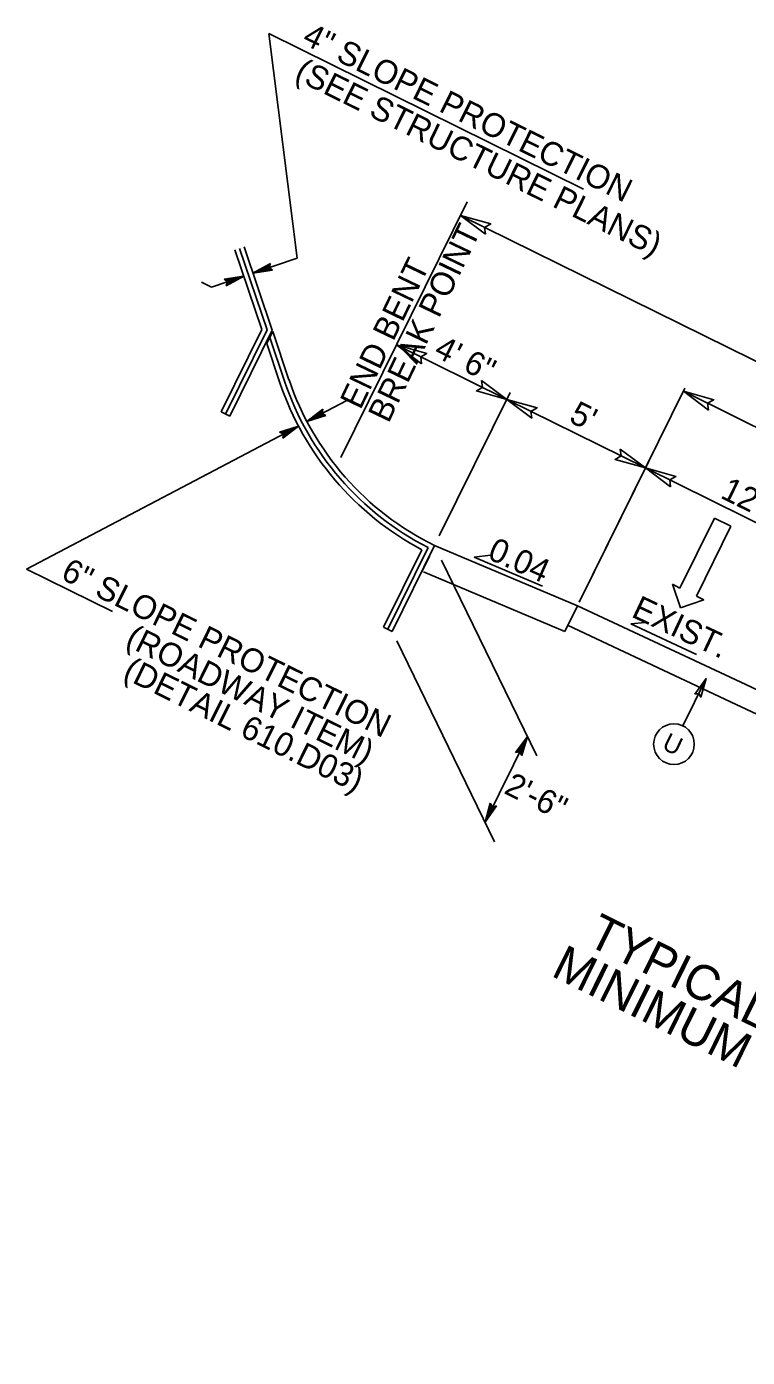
# Model space of a CAD drawing. Extents: x 1518247 to 1523638, y 635234 to 639927.
# Drawn here: x 1518247 to 1518587, y 636846 to 637473 of the extents above; entities that cross this region are included whole.
import ezdxf

# ---------------------------------------------------------------- set-up
doc = ezdxf.new("R2010")
doc.units = 0
for name, color, linetype in [('DTM TIN Hull White', 7, 'Continuous'), ('Prop Dimension', 7, 'Continuous'), ('Prop Dimension Text', 7, 'Continuous'), ('Prop Lane Arrow CELL', 7, 'Continuous'), ('Prop Shade Light', 7, 'Continuous'), ('Typical ID Circle CELL', 7, 'Continuous'), ('Typical Pavement Slope CELL', 7, 'Continuous'), ('Typical Pavement Slope Information CELL', 7, 'Continuous'), ('Typical Structure Recommendation Sheet 2 CELL', 7, 'Continuous'), ('Typical Text ID Circle CELL', 7, 'Continuous')]:
    doc.layers.add(name, color=color, linetype=linetype)

# ---------------------------------------------------------------- blocks, each defined once
blk = doc.blocks.new('TERMINATOR')
at = {"layer": 'Prop Shade Light'}
blk.add_lwpolyline([(-0.469, 0.081), (0, 0), (-0.471, -0.083), (-0.411, 0)], close=True, dxfattribs=at)

msp = doc.modelspace()

# ---------------------------------------------------------------- linework, layer by layer
at = {"layer": 'DTM TIN Hull White'}
for p, q in [((1518506.56, 637199.95), (1518585.79, 637162.77)), ((1518502.16, 637190.56), (1518581.38, 637153.38)), ((1518585.79, 637162.77), (1518665.01, 637125.59)), ((1518581.38, 637153.38), (1518660.6, 637116.2))]:
    msp.add_line(p, q, dxfattribs=at)
at = {"layer": 'Prop Dimension'}
for p, q in [((1518361.13, 637469.46), (1518509.42, 637396.2)), ((1518361.13, 637469.46), (1518374.56, 637363.71)), ((1518454.64, 637390.29), (1518395.09, 637269.74)), ((1518451.43, 637383.79), (1518816.55, 637203.43)), ((1518353.69, 637356.62), (1518374.56, 637363.71)), ((1518334.11, 637350.03), (1518349.34, 637355.16)), ((1518334.11, 637350.03), (1518329.48, 637352.31)), ((1518421.3, 637322.79), (1518473.22, 637297.14)), ((1518507.41, 637201.65), (1518557.16, 637302.38)), ((1518379.13, 637286.69), (1518397.9, 637296.6)), ((1518441.44, 637232.81), (1518474.84, 637300.41)), ((1518473.22, 637297.14), (1518538.55, 637264.87)), ((1518713.35, 637223.45), (1518556.46, 637300.95)), ((1518247.07, 637217.1), (1518375.13, 637284.6)), ((1518508.18, 637203.22), (1518540.23, 637268.11)), ((1518508.18, 637203.22), (1518540.23, 637268.11)), ((1518538.62, 637264.84), (1518617.06, 637226.09)), ((1518442.55, 637221.45), (1518487.47, 637129.21)), ((1518247.07, 637217.1), (1518287.47, 637197.14)), ((1518421.39, 637183.38), (1518467.48, 637088.72)), ((1518463.02, 637097.88), (1518483.01, 637138.36))]:
    msp.add_line(p, q, dxfattribs=at)
at = {"layer": 'Prop Lane Arrow CELL'}
for p, q in [((1518554.82, 637208.27), (1518571.1, 637241.23)), ((1518571.1, 637241.23), (1518578.87, 637237.39)), ((1518578.87, 637237.39), (1518562.59, 637204.43)), ((1518555.16, 637198.88), (1518551.29, 637210.01)), ((1518551.29, 637210.01), (1518554.82, 637208.27)), ((1518566.12, 637202.69), (1518555.16, 637198.88)), ((1518562.59, 637204.43), (1518566.12, 637202.69))]:
    msp.add_line(p, q, dxfattribs=at)
at = {"layer": 'Prop Shade Light'}
msp.add_lwpolyline([(1518561.85, 637158.26), (1518567.13, 637165.56), (1518564.62, 637156.85), (1518563.7, 637158.56)], close=True, dxfattribs=at)
at = {"layer": 'Typical ID Circle CELL'}
msp.add_line((1518556.22, 637143.31), (1518567.13, 637165.56), dxfattribs=at)
msp.add_circle((1518552.01, 637134.7), 9.59, dxfattribs=at)
at = {"layer": 'Typical Pavement Slope CELL'}
for p, q in [((1518506.56, 637199.95), (1518439.23, 637228.33)), ((1518436.34, 637222.52), (1518433.07, 637215.89)), ((1518436.86, 637223.24), (1518433.24, 637215.91)), ((1518500.64, 637187.81), (1518433.99, 637215.9)), ((1518506.56, 637199.95), (1518500.64, 637187.81))]:
    msp.add_line(p, q, dxfattribs=at)
at = {"layer": 'Typical Pavement Slope Information CELL'}
for p, q in [((1518457.89, 637222.76), (1518465.63, 637223.73)), ((1518457.89, 637222.76), (1518490.05, 637209.21)), ((1518531.77, 637191.47), (1518538.42, 637192.03)), ((1518531.77, 637191.47), (1518562.55, 637177.02))]:
    msp.add_line(p, q, dxfattribs=at)
at = {"layer": 'Typical Structure Recommendation Sheet 2 CELL'}
for p, q in [((1518357.89, 637330.02), (1518345.17, 637367.53)), ((1518360.35, 637329.87), (1518347.33, 637368.31)), ((1518362.78, 637329.69), (1518349.48, 637369)), ((1518353.69, 637356.62), (1518361.88, 637361.13)), ((1518361.8, 637360.9), (1518353.69, 637356.62)), ((1518353.69, 637356.62), (1518361.71, 637360.59)), ((1518361.61, 637360.33), (1518353.69, 637356.62)), ((1518353.69, 637356.62), (1518361.53, 637360.04)), ((1518361.47, 637359.75), (1518353.69, 637356.62)), ((1518353.69, 637356.62), (1518361.38, 637359.5)), ((1518361.27, 637359.23), (1518353.69, 637356.62)), ((1518361.49, 637359.02), (1518353.69, 637356.62)), ((1518353.69, 637356.62), (1518361.75, 637358.87)), ((1518361.88, 637361.13), (1518361.27, 637359.23)), ((1518361.27, 637359.23), (1518362.94, 637358.04)), ((1518349.34, 637355.16), (1518340.08, 637353.8)), ((1518341.75, 637352.62), (1518340.08, 637353.8)), ((1518349.34, 637355.16), (1518340.31, 637353.6)), ((1518340.56, 637353.44), (1518349.34, 637355.16)), ((1518349.34, 637355.16), (1518340.81, 637353.28)), ((1518341.01, 637353.1), (1518349.34, 637355.16)), ((1518349.34, 637355.16), (1518341.14, 637350.66)), ((1518341.14, 637350.66), (1518341.75, 637352.62)), ((1518341.21, 637350.98), (1518349.34, 637355.16)), ((1518349.34, 637355.16), (1518341.25, 637352.93)), ((1518349.34, 637355.16), (1518341.33, 637351.22)), ((1518341.37, 637351.5), (1518349.34, 637355.16)), ((1518349.34, 637355.16), (1518341.49, 637351.77)), ((1518341.51, 637352.8), (1518349.34, 637355.16)), ((1518341.57, 637352.05), (1518349.34, 637355.16)), ((1518349.34, 637355.16), (1518341.67, 637352.33)), ((1518341.75, 637352.62), (1518349.34, 637355.16)), ((1518361.98, 637358.72), (1518353.69, 637356.62)), ((1518353.69, 637356.62), (1518362.23, 637358.58)), ((1518362.44, 637358.36), (1518353.69, 637356.62)), ((1518353.69, 637356.62), (1518362.69, 637358.2)), ((1518353.69, 637356.62), (1518362.94, 637358.04)), ((1518357.89, 637330.02), (1518338.73, 637291.23)), ((1518360.35, 637329.87), (1518340.76, 637290.23)), ((1518362.78, 637329.69), (1518342.8, 637289.22)), ((1518362.99, 637329.14), (1518360.16, 637323.4)), ((1518370.66, 637306.42), (1518362.99, 637329.14)), ((1518366.39, 637304.97), (1518360.16, 637323.4)), ((1518368.51, 637305.73), (1518361.56, 637326.24)), ((1518342.8, 637289.22), (1518338.73, 637291.23)), ((1518379.13, 637286.69), (1518386.56, 637292.48)), ((1518386.51, 637292.18), (1518379.13, 637286.69)), ((1518379.13, 637286.69), (1518386.47, 637291.87)), ((1518386.4, 637291.61), (1518379.13, 637286.69)), ((1518379.13, 637286.69), (1518386.39, 637291.34)), ((1518386.33, 637291.04), (1518379.13, 637286.69)), ((1518379.13, 637286.69), (1518386.27, 637290.75)), ((1518386.26, 637290.42), (1518379.13, 637286.69)), ((1518386.48, 637290.32), (1518379.13, 637286.69)), ((1518379.13, 637286.69), (1518386.77, 637290.17)), ((1518387.01, 637290.06), (1518379.13, 637286.69)), ((1518379.13, 637286.69), (1518387.29, 637289.92)), ((1518386.56, 637292.48), (1518386.26, 637290.42)), ((1518386.26, 637290.42), (1518388.06, 637289.54)), ((1518375.13, 637284.6), (1518366.2, 637281.73)), ((1518375.13, 637284.6), (1518366.48, 637281.59)), ((1518366.72, 637281.48), (1518375.13, 637284.6)), ((1518375.13, 637284.6), (1518367.01, 637281.33)), ((1518367.23, 637281.23), (1518375.13, 637284.6)), ((1518375.13, 637284.6), (1518367.51, 637281.09)), ((1518375.13, 637284.6), (1518367.73, 637278.84)), ((1518367.75, 637280.97), (1518375.13, 637284.6)), ((1518367.77, 637279.15), (1518375.13, 637284.6)), ((1518375.13, 637284.6), (1518367.81, 637279.4)), ((1518367.85, 637279.73), (1518375.13, 637284.6)), ((1518367.9, 637280.24), (1518375.13, 637284.6)), ((1518375.13, 637284.6), (1518367.92, 637280)), ((1518375.13, 637284.6), (1518367.97, 637280.57)), ((1518368.05, 637280.86), (1518375.13, 637284.6)), ((1518387.55, 637289.79), (1518379.13, 637286.69)), ((1518379.13, 637286.69), (1518387.8, 637289.67)), ((1518379.13, 637286.69), (1518388.06, 637289.54)), ((1518368.05, 637280.86), (1518366.2, 637281.73)), ((1518367.73, 637278.84), (1518368.05, 637280.86)), ((1518436.2, 637227.3), (1518417.19, 637188.82)), ((1518439.23, 637228.33), (1518419.22, 637187.82)), ((1518439.23, 637228.33), (1518437.89, 637225.61)), ((1518433.17, 637226.33), (1518415.14, 637189.84)), ((1518419.22, 637187.82), (1518415.14, 637189.84)), ((1518483.01, 637138.36), (1518477.38, 637130.82)), ((1518483.01, 637138.36), (1518477.67, 637130.86)), ((1518477.96, 637130.89), (1518483.01, 637138.36)), ((1518483.01, 637138.36), (1518478.26, 637130.95)), ((1518478.55, 637131.01), (1518483.01, 637138.36)), ((1518483.01, 637138.36), (1518478.82, 637131.06)), ((1518479.11, 637131.11), (1518483.01, 637138.36)), ((1518479.38, 637131.16), (1518483.01, 637138.36)), ((1518483.01, 637138.36), (1518479.53, 637130.9)), ((1518479.67, 637130.63), (1518483.01, 637138.36)), ((1518483.01, 637138.36), (1518479.76, 637130.39)), ((1518479.92, 637130.12), (1518483.01, 637138.36)), ((1518483.01, 637138.36), (1518480, 637129.86)), ((1518480.16, 637129.6), (1518483.01, 637138.36)), ((1518483.01, 637138.36), (1518480.3, 637129.35)), ((1518479.38, 637131.16), (1518477.38, 637130.82)), ((1518480.3, 637129.35), (1518479.38, 637131.16)), ((1518463.02, 637097.88), (1518465.48, 637106.97)), ((1518465.62, 637106.72), (1518463.02, 637097.88)), ((1518463.02, 637097.88), (1518465.79, 637106.47)), ((1518465.88, 637106.21), (1518463.02, 637097.88)), ((1518463.02, 637097.88), (1518466.05, 637105.94)), ((1518466.15, 637105.71), (1518463.02, 637097.88)), ((1518463.02, 637097.88), (1518468.44, 637105.58)), ((1518463.02, 637097.88), (1518468.15, 637105.53)), ((1518467.86, 637105.49), (1518463.02, 637097.88)), ((1518463.02, 637097.88), (1518466.29, 637105.45)), ((1518463.02, 637097.88), (1518467.56, 637105.42)), ((1518467.28, 637105.36), (1518463.02, 637097.88)), ((1518463.02, 637097.88), (1518467.01, 637105.3)), ((1518466.71, 637105.24), (1518463.02, 637097.88)), ((1518466.45, 637105.18), (1518463.02, 637097.88)), ((1518465.48, 637106.97), (1518466.45, 637105.18)), ((1518466.45, 637105.18), (1518468.44, 637105.58))]:
    msp.add_line(p, q, dxfattribs=at)
for radius, start, end in [(139.92, 198.71188, 241.983), (137.66, 198.71189, 242.89418), (135.41, 198.71189, 243.83552)]:
    msp.add_arc((1518498.92, 637349.85), radius, start, end, dxfattribs=at)

# ---------------------------------------------------------------- block references
at = {"layer": 'Prop Dimension', "xscale": 30.9388560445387, "yscale": 33.305184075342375}
for p, rotation in [((1518451.43, 637383.79), 153.71146049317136), ((1518421.3, 637322.79), 153.71146049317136), ((1518473.22, 637297.14), -26.28853950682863), ((1518556.46, 637300.95), 153.71146049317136), ((1518473.22, 637297.14), 153.71146049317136), ((1518538.55, 637264.87), -26.28853950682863), ((1518538.62, 637264.84), 153.71146049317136)]:
    msp.add_blockref('TERMINATOR', p, dxfattribs=dict(at, rotation=rotation))

# ---------------------------------------------------------------- texts
at = {"layer": 'Prop Dimension'}
for s, p in [('4\' 6"', (1518438.38, 637317.7)), ("5'", (1518502.02, 637286.78)), ("12'", (1518573.34, 637250.99))]:
    msp.add_text(s, height=11.189, rotation=333.71146, dxfattribs=at).set_placement(p)
at = {"layer": 'Prop Dimension Text'}
for s, p in [('TYPICAL SECTION UNDER STRUCTURE', (1518510.23, 637040.52)), ('MINIMUM VERTICAL CLEARANCE 16\' 6"', (1518493.58, 637025.75))]:
    msp.add_text(s, height=16.5769, rotation=333.71146, dxfattribs=at).set_placement(p)
at = {"layer": 'Typical Pavement Slope CELL'}
msp.add_text('0.04 ', height=11.189, rotation=336.00289, dxfattribs=at).set_placement((1518463.62, 637222.28))
at = {"layer": 'Typical Pavement Slope Information CELL'}
for s, height, rotation, p in [('4" SLOPE PROTECTION', 11.1894, 333.71146, (1518376.33, 637464.98)), ('(SEE STRUCTURE PLANS)', 11.1894, 333.71146, (1518372.7, 637448.23)), ('6" SLOPE PROTECTION ', 11.1894, 333.71146, (1518262.65, 637212.78)), ('EXIST.', 11.189, 334.8572, (1518531.44, 637194.92)), ('(ROADWAY ITEM)', 11.1894, 333.71146, (1518292.99, 637181.43))]:
    msp.add_text(s, height=height, rotation=rotation, dxfattribs=at).set_placement(p)
at = {"layer": 'Typical Structure Recommendation Sheet 2 CELL'}
for s, height, rotation, p in [('BREAK POINT', 11.1894, 64.38509, (1518417.55, 637285.52)), ('END BENT', 11.189, 64.38509, (1518404.32, 637291.86)), ('(DETAIL 610.D03)', 11.1894, 333.71146, (1518291.86, 637166.14)), ('2\'-6"', 11.189, 333.71146, (1518471.37, 637111.78))]:
    msp.add_text(s, height=height, rotation=rotation, dxfattribs=at).set_placement(p)
at = {"layer": 'Typical Text ID Circle CELL'}
msp.add_text('U', height=8.58, rotation=333.89618, dxfattribs=at).set_placement((1518545.86, 637132.67))

doc.saveas('drawing.dxf')
